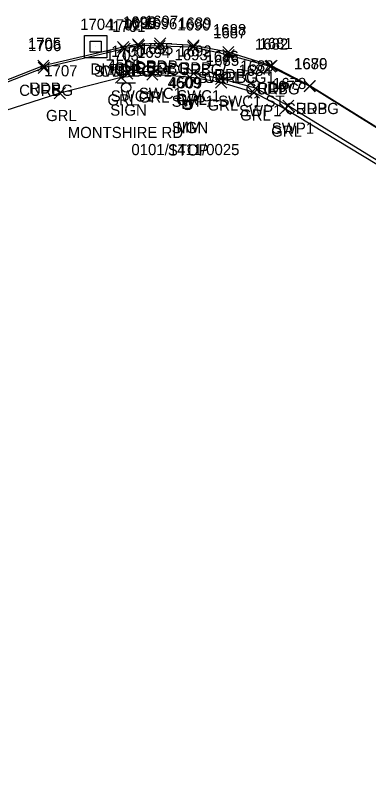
# Model space of a CAD drawing. Extents: x 1690689 to 1696275, y 438760 to 444007.
# Drawn here: x 1691909.9 to 1691973.1, y 439004.8 to 439143.3 of the extents above; entities that cross this region are included whole.
import ezdxf

# ---------------------------------------------------------------- set-up
doc = ezdxf.new("R2010")
doc.units = 0
for name, color, linetype in [('D_A', 7, 'Continuous'), ('D_I', 7, 'Continuous'), ('DS', 7, 'Continuous'), ('P_A', 7, 'Continuous'), ('P_I', 7, 'Continuous'), ('P_TIC', 7, 'Continuous'), ('PET', 7, 'Continuous'), ('R_A', 7, 'Continuous'), ('R_I', 7, 'Continuous'), ('R_TIC', 7, 'Continuous'), ('RC', 7, 'Continuous'), ('RGR', 7, 'Continuous'), ('RSW', 7, 'Continuous'), ('S_A', 7, 'Continuous'), ('S_C', 7, 'Continuous'), ('S_I', 7, 'Continuous'), ('SRM', 7, 'Continuous'), ('SSGN', 7, 'Continuous')]:
    doc.layers.add(name, color=color, linetype=linetype)

msp = doc.modelspace()

# ---------------------------------------------------------------- linework, layer by layer
at = {"layer": 'DS'}
for p, q in [((1691922.23, 439139.69), (1691926.23, 439139.69)), ((1691922.23, 439135.69), (1691922.23, 439139.69)), ((1691926.23, 439139.69), (1691926.23, 439135.69)), ((1691923.23, 439136.69), (1691923.23, 439138.69)), ((1691923.23, 439138.69), (1691925.23, 439138.69)), ((1691924.23, 439137.7), (1691924.23, 439137.7)), ((1691924.23, 439137.7), (1691924.23, 439137.7)), ((1691925.23, 439138.69), (1691925.23, 439136.69)), ((1691925.23, 439136.69), (1691923.23, 439136.69)), ((1691926.23, 439135.69), (1691922.23, 439135.69))]:
    msp.add_line(p, q, dxfattribs=at)
at = {"layer": 'P_TIC'}
for points in [[(1691930.84, 439137.11), (1691932.84, 439139.11)], [(1691932.84, 439137.11), (1691930.84, 439139.11)], [(1691934.77, 439137.24), (1691936.77, 439139.24)], [(1691936.77, 439137.24), (1691934.77, 439139.24)], [(1691940.75, 439136.91), (1691942.75, 439138.91)], [(1691942.75, 439136.91), (1691940.75, 439138.91)], [(1691928.14, 439136.6), (1691930.14, 439138.6)], [(1691930.14, 439136.6), (1691928.14, 439138.6)], [(1691946.97, 439135.72), (1691948.97, 439137.72)], [(1691948.97, 439135.72), (1691946.97, 439137.72)], [(1691913.86, 439133.28), (1691915.86, 439135.28)], [(1691915.86, 439133.28), (1691913.86, 439135.28)], [(1691913.86, 439133.28), (1691915.86, 439135.28)], [(1691915.86, 439133.28), (1691913.86, 439135.28)], [(1691954.71, 439133.26), (1691956.71, 439135.26)], [(1691956.71, 439133.26), (1691954.71, 439135.26)], [(1691961.57, 439129.66), (1691963.57, 439131.66)], [(1691963.57, 439129.66), (1691961.57, 439131.66)]]:
    msp.add_lwpolyline(points, dxfattribs=at)
at = {"layer": 'PET'}
for points in [[(1692485.07, 438945.57), (1692435.03, 438955.4), (1692385.23, 438965.25), (1692340.43, 438974.31), (1692296.87, 438984.77), (1692272.43, 438991.45), (1692235.97, 439002.41), (1692197.17, 439015.62), (1692153.62, 439031.87), (1692118.48, 439046.77), (1692081.06, 439063.89), (1692043.59, 439082.96), (1692015.06, 439098.81), (1691980.04, 439119.84), (1691962.57, 439130.66), (1691955.71, 439134.26), (1691947.97, 439136.72), (1691941.75, 439137.91), (1691935.77, 439138.24), (1691931.84, 439138.11), (1691929.14, 439137.6), (1691914.86, 439134.28)], [(1691914.86, 439134.28), (1691889.47, 439124.28), (1691873.84, 439117.79), (1691827.5, 439101.68)]]:
    msp.add_lwpolyline(points, dxfattribs=at)
at = {"layer": 'R_TIC'}
for points in [[(1691930.95, 439136.88), (1691932.95, 439138.88)], [(1691932.95, 439136.88), (1691930.95, 439138.88)], [(1691934.68, 439136.8), (1691936.68, 439138.8)], [(1691936.68, 439136.8), (1691934.68, 439138.8)], [(1691928.4, 439136.32), (1691930.4, 439138.32)], [(1691930.4, 439136.32), (1691928.4, 439138.32)], [(1691928.4, 439136.32), (1691930.4, 439138.32)], [(1691930.4, 439136.32), (1691928.4, 439138.32)], [(1691940.67, 439136.59), (1691942.67, 439138.59)], [(1691942.67, 439136.59), (1691940.67, 439138.59)], [(1691947, 439135.19), (1691949, 439137.19)], [(1691949, 439135.19), (1691947, 439137.19)], [(1691947, 439135.19), (1691949, 439137.19)], [(1691949, 439135.19), (1691947, 439137.19)], [(1691913.96, 439132.89), (1691915.96, 439134.89)], [(1691915.96, 439132.89), (1691913.96, 439134.89)], [(1691954.49, 439133.15), (1691956.49, 439135.15)], [(1691956.49, 439133.15), (1691954.49, 439135.15)], [(1691928.89, 439131.87), (1691930.89, 439133.87)], [(1691930.89, 439131.87), (1691928.89, 439133.87)], [(1691933.38, 439131.69), (1691935.38, 439133.69)], [(1691935.38, 439131.69), (1691933.38, 439133.69)], [(1691933.91, 439132.34), (1691935.91, 439134.34)], [(1691935.91, 439132.34), (1691933.91, 439134.34)], [(1691940.09, 439131.25), (1691942.09, 439133.25)], [(1691942.09, 439131.25), (1691940.09, 439133.25)], [(1691940.77, 439131.91), (1691942.77, 439133.91)], [(1691942.77, 439131.91), (1691940.77, 439133.91)], [(1691927.78, 439131.18), (1691929.78, 439133.18)], [(1691929.78, 439131.18), (1691927.78, 439133.18)], [(1691945.68, 439130.94), (1691947.68, 439132.94)], [(1691947.68, 439130.94), (1691945.68, 439132.94)], [(1691945.68, 439130.94), (1691947.68, 439132.94)], [(1691947.68, 439130.94), (1691945.68, 439132.94)], [(1691945.71, 439130.26), (1691947.71, 439132.26)], [(1691947.71, 439130.26), (1691945.71, 439132.26)], [(1691951.53, 439128.47), (1691953.53, 439130.47)], [(1691953.53, 439128.47), (1691951.53, 439130.47)], [(1691951.86, 439129.25), (1691953.86, 439131.25)], [(1691953.86, 439129.25), (1691951.86, 439131.25)], [(1691961.53, 439129.63), (1691963.53, 439131.63)], [(1691963.53, 439129.63), (1691961.53, 439131.63)], [(1691916.8, 439128.38), (1691918.8, 439130.38)], [(1691918.8, 439128.38), (1691916.8, 439130.38)], [(1691957.72, 439126.11), (1691959.72, 439128.11)], [(1691959.72, 439126.11), (1691957.72, 439128.11)], [(1691957.12, 439125.58), (1691959.12, 439127.58)], [(1691959.12, 439125.58), (1691957.12, 439127.58)]]:
    msp.add_lwpolyline(points, dxfattribs=at)
at = {"layer": 'RC'}
msp.add_lwpolyline([(1692118.26, 439046.46), (1692080.62, 439063.88), (1692043.41, 439082.64), (1692014.87, 439098.55), (1691980.03, 439119.7), (1691962.53, 439130.63), (1691955.49, 439134.15), (1691948, 439136.19), (1691941.67, 439137.59), (1691935.68, 439137.8), (1691931.95, 439137.88), (1691929.4, 439137.32), (1691914.96, 439133.89), (1691889.69, 439124), (1691873.84, 439117.58), (1691827.75, 439101.2)], dxfattribs=at)
at = {"layer": 'RGR'}
msp.add_lwpolyline([(1692115.78, 439041.61), (1692078.11, 439058.76), (1692039.55, 439079.01), (1692012.2, 439093.97), (1691976.83, 439115.26), (1691958.12, 439126.58), (1691952.53, 439129.47), (1691946.71, 439131.26), (1691941.09, 439132.25), (1691934.38, 439132.69), (1691928.78, 439132.18), (1691917.8, 439129.38), (1691893.03, 439121.47), (1691884.65, 439119.11), (1691880.06, 439116.74), (1691874.97, 439112.92)], dxfattribs=at)
at = {"layer": 'RSW'}
for points in [[(1691946.68, 439131.94), (1691941.77, 439132.91), (1691934.91, 439133.34), (1691929.89, 439132.87), (1691929.4, 439137.32)], [(1692637.9, 438909.12), (1692604.66, 438916.25), (1692559.9, 438925.87), (1692526.71, 438932.34), (1692484.3, 438940.72), (1692434.26, 438950.4), (1692384.3, 438960.21), (1692339.45, 438969.35), (1692295.64, 438980.27), (1692271.48, 438986.87), (1692234.38, 438997.66), (1692195.38, 439010.77), (1692151.68, 439027.12), (1692116.08, 439041.96), (1692078.43, 439059.23), (1692041.02, 439078.87), (1692012.59, 439094.44), (1691977.25, 439115.7), (1691958.72, 439127.11), (1691952.86, 439130.25), (1691946.68, 439131.94), (1691948, 439136.19)]]:
    msp.add_lwpolyline(points, dxfattribs=at)
at = {"layer": 'SRM'}
msp.add_lwpolyline([(1691939.88, 439127.91), (1691941.13, 439127.91), (1691941.13, 439126.66), (1691939.88, 439126.66)], close=True, dxfattribs=at)
msp.add_circle((1691940.51, 439127.29), 0.0833, dxfattribs=at)
at = {"layer": 'SSGN'}
for p, q in [((1691928.05, 439131.2), (1691931.39, 439131.2)), ((1691929.7, 439130.37), (1691929.7, 439130.37)), ((1691939.05, 439128.07), (1691942.39, 439128.07)), ((1691940.7, 439127.24), (1691940.7, 439127.24))]:
    msp.add_line(p, q, dxfattribs=at)
for centre in [(1691929.7, 439130.37), (1691940.7, 439127.24)]:
    msp.add_circle(centre, 0.833, dxfattribs=at)

# ---------------------------------------------------------------- texts
at = {"layer": 'D_A'}
msp.add_text('DI', height=2, dxfattribs=at).set_placement((1691923.29, 439132.7))
at = {"layer": 'D_I'}
msp.add_text('1704', height=2, dxfattribs=at).set_placement((1691921.46, 439140.7))
at = {"layer": 'P_A'}
for p in [(1691929.33, 439133.11), (1691933.25, 439133.24), (1691939.24, 439132.91), (1691926.63, 439132.6), (1691945.46, 439131.72), (1691912.34, 439129.28), (1691912.34, 439129.28), (1691953.2, 439129.26), (1691960.06, 439125.66)]:
    msp.add_text('RDP', height=2, dxfattribs=at).set_placement(p)
at = {"layer": 'P_I'}
for s, p in [('1698', (1691929.1, 439141.11)), ('1697', (1691933.03, 439141.24)), ('1689', (1691939.01, 439140.91)), ('1702', (1691926.37, 439140.6)), ('1688', (1691945.23, 439139.72)), ('1705', (1691912.08, 439137.28)), ('1705', (1691912.08, 439137.28)), ('1681', (1691953.54, 439137.26)), ('1680', (1691959.74, 439133.66))]:
    msp.add_text(s, height=2, dxfattribs=at).set_placement(p)
at = {"layer": 'R_A'}
for s, p in [('CURBG', (1691927.54, 439132.88)), ('CURBG', (1691931.26, 439132.8)), ('CURBG', (1691937.25, 439132.59)), ('SWC1 CG1', (1691923.89, 439132.32)), ('CURBG', (1691924.98, 439132.32)), ('SWP1 CG1', (1691942.49, 439131.19)), ('CURBG', (1691943.59, 439131.19)), ('CURBG', (1691910.54, 439128.89)), ('CURBG', (1691951.07, 439129.15)), ('GRL', (1691926.33, 439127.18)), ('SWC1', (1691926.93, 439127.87)), ('GRL', (1691931.93, 439127.69)), ('SWC1', (1691931.95, 439128.34)), ('GRL', (1691938.64, 439127.25)), ('SWC1', (1691938.81, 439127.91)), ('SWP1 SWC1 ST', (1691937.84, 439126.94)), ('SWP1 SWC1 ST', (1691937.84, 439126.94)), ('GRL', (1691944.26, 439126.26)), ('GRL', (1691915.34, 439124.38)), ('SWP1', (1691949.9, 439125.25)), ('GRL', (1691950.08, 439124.47)), ('CURBG', (1691958.11, 439125.63)), ('GRL', (1691955.66, 439121.58)), ('SWP1', (1691955.76, 439122.11))]:
    msp.add_text(s, height=2, dxfattribs=at).set_placement(p)
at = {"layer": 'R_I'}
for s, p in [('1701', (1691927.19, 439140.32)), ('1701', (1691927.19, 439140.32)), ('1699', (1691929.21, 439140.88)), ('1696', (1691932.89, 439140.8)), ('1690', (1691938.84, 439140.59)), ('1687', (1691945.26, 439139.19)), ('1687', (1691945.26, 439139.19)), ('1706', (1691912.13, 439136.89)), ('1682', (1691952.75, 439137.15)), ('1700', (1691927.03, 439135.87)), ('1694', (1691931.64, 439135.69)), ('1695', (1691932.17, 439136.34)), ('1692', (1691939.03, 439135.91)), ('1703', (1691926.01, 439135.18)), ('1693', (1691938.35, 439135.25)), ('1686', (1691943.88, 439134.94)), ('1686', (1691943.88, 439134.94)), ('1685', (1691943.97, 439134.26)), ('1683', (1691950.12, 439133.25)), ('1679', (1691959.78, 439133.63)), ('1707', (1691915.03, 439132.38)), ('1684', (1691949.79, 439132.47)), ('1678', (1691955.98, 439130.11)), ('1677', (1691955.38, 439129.58))]:
    msp.add_text(s, height=2, dxfattribs=at).set_placement(p)
at = {"layer": 'S_A'}
for s, p in [('SIGN', (1691926.84, 439125.35)), ('SIGN', (1691937.84, 439122.22)), ('MM', (1691938.7, 439122.29))]:
    msp.add_text(s, height=2, dxfattribs=at).set_placement(p)
at = {"layer": 'S_C'}
for s, p in [('MONTSHIRE RD', (1691919.23, 439121.35)), ('0101/1411/0025', (1691930.63, 439118.29)), ('STOP', (1691937.16, 439118.22))]:
    msp.add_text(s, height=2, dxfattribs=at).set_placement(p)
at = {"layer": 'S_I'}
for s, p in [('4508', (1691926.34, 439133.35)), ('4609', (1691937.11, 439130.29)), ('4509', (1691937.34, 439130.22))]:
    msp.add_text(s, height=2, dxfattribs=at).set_placement(p)

doc.saveas('drawing.dxf')
